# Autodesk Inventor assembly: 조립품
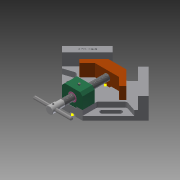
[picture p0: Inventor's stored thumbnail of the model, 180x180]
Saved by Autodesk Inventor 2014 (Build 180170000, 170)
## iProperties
Created: 2019-04
Part Number: 조립품
Document SubType Name: Assembly
Designer: kh
Author: kh
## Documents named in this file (11)
- C:\Users\kh\Desktop\490407V1007\조립품.iam
- C:\Users\kh\Desktop\490407V1007\490407V1007.ipt
- C:\Users\kh\Desktop\490407V1007\리드스크류.ipt
- C:\Users\kh\Desktop\490407V1007\멈춤나사 M4x5.ipt
- C:\Users\kh\Desktop\490407V1007\멈춤나사 M4x10.ipt
- C:\Users\kh\Desktop\490407V1007\볼트 M4x16.ipt
- C:\Users\kh\Desktop\490407V1007\부시.ipt
- C:\Users\kh\Desktop\490407V1007\서포트.ipt
- C:\Users\kh\Desktop\490407V1007\조.ipt
- C:\Users\kh\Desktop\490407V1007\평행 핀 2.5x24.ipt
- C:\Users\kh\Desktop\490407V1007\핸들.ipt
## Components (2 placed, 2 different names)
1. 490407V1007:1 — Insert:1, Insert:2, Mate:4, Mate:5, Insert:4, Angle:1, Mate:10
2. 핸들:1 — Cylindrical:1, Mate:1, Mate:3
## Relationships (10: Mate 5, Insert 3, CylindricalJoint 1, Angle 1)
- Insert:1: 490407V1007:1
- Insert:2: 490407V1007:1
- Cylindrical:1: 핸들:1
- Mate:1: 핸들:1
- Mate:3: 핸들:1
- Mate:4: 490407V1007:1
- Mate:5: 490407V1007:1
- Insert:4: 490407V1007:1
- Angle:1: 490407V1007:1
- Mate:10: 490407V1007:1
